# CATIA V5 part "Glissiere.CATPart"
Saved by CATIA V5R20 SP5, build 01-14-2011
Part number: Glissière
Bounding box of the stored display mesh (mm): x -47.378 to 2.583, y -80.309 to -8.71, z 3 to 6
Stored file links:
  D:\thinkmotion-MPB\Dropbox\IAO_2011\MMS_GR3\IAO_2011_1523_mkessler\mkessler\mkessler_IAO\mkessler_INIT\Glissiere.CATPart
  D:\thinkmotion-MPB\Dropbox\IAO_2011\MMS_GR3\IAO_2011_1523_mkessler\mkessler\mkessler_IAO\mkessler_INIT\Squelette_glissiere_1.CATPart
  C:\Users\MARLENE\Documents\IFMA\S3\IAO\Copie de CAO\Assemblage_final.CATProduct
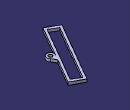
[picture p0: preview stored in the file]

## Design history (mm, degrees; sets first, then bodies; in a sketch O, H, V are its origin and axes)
External parameters (linked from other documents)
  External.Longueur_int_glissiere_1 = 68 mm
  External.Largeur_int_glissiere_1 = 10 mm
  External.Longueur_ext_glissiere_1 = 74 mm
  External.Largeur_ext_glissiere_1 = 15 mm
Set1
  Plane1: linked copy from another document
  Line1 to Line4: linked copy from another document
  Point1: linked copy from another document
  Line5 to Line7: linked copy from another document
Body1 (main body)
  Sketch1 on Plane1, origin (0, 0, 3), H (1, 0, 0), V (0, 1, 0)
    projected line E1 (2.5827, -16.2036) -> (-10.4116, -8.7104) from Line4
    point P1 (2.5827, -16.2036)
    projected line E2 (-10.4116, -8.7104) -> (-47.3783, -72.8154) from Line3
    projected line E3 (-34.3841, -80.3087) -> (2.5827, -16.2036) from Line5
    projected line E4 (-34.3841, -80.3087) -> (-15.9007, -48.2562) from Line5
    projected line E5 (-12.4355, -42.2472) -> (2.5827, -16.2036) from Line5
    point P5 (-34.3841, -80.3087)
    point P6 (2.5827, -16.2036)
    projected line E6 (-34.3841, -80.3087) -> (-47.3783, -72.8154) from Line6
    point P7 (-34.3841, -80.3087)
    projected line E7 (-9.7445, -12.5581) -> (-1.0817, -17.5536) from Line1
    point P9 (-9.7445, -12.5581)
    projected line E8 (-1.0817, -17.5536) -> (-35.0511, -76.461) from Line2
    projected line E9 (-35.0511, -76.461) -> (-43.714, -71.4654) from Line7
    point P14 (-43.714, -71.4654)
    line L1 (-9.7445, -12.5581) -> (-43.714, -71.4654)
    point P15 (-9.7445, -12.5581)
    point P16 (-43.714, -71.4654)
    arc A1 centre (-12.4355, -50.2544) radius 4 from (-15.9007, -48.2562) to (-9.7445, -47.2949) ccw
    circle A2 centre (-12.4355, -50.2544) radius 2
    reference projected point E10 (-12.4355, -50.2544) from Point1
    reference projected point E11 (-12.4355, -50.2544) from Point1
    spline S1 through (-9.7445, -47.2949) (-12.4355, -42.2472)
    point P19 (-15.9007, -48.2562)
    point P20 (-9.7445, -47.2949)
    point P21 (-12.4355, -42.2472)
    point P22 (-9.7445, -47.2949)
    point P23 (-12.4355, -42.2472)
    radius A2 = 2
    radius A1 = 4
    coincidence: P15 E7, P16 E9, P22 A1, P23 E3, P22 P20, E3 P19, P23 P21, P1 P6, P5 P7, P9 P15, P14 P16
    concentricity: E10 A2, E11 A1
  Pad1: profile Sketch1, direction (0, 0, 1), length 3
